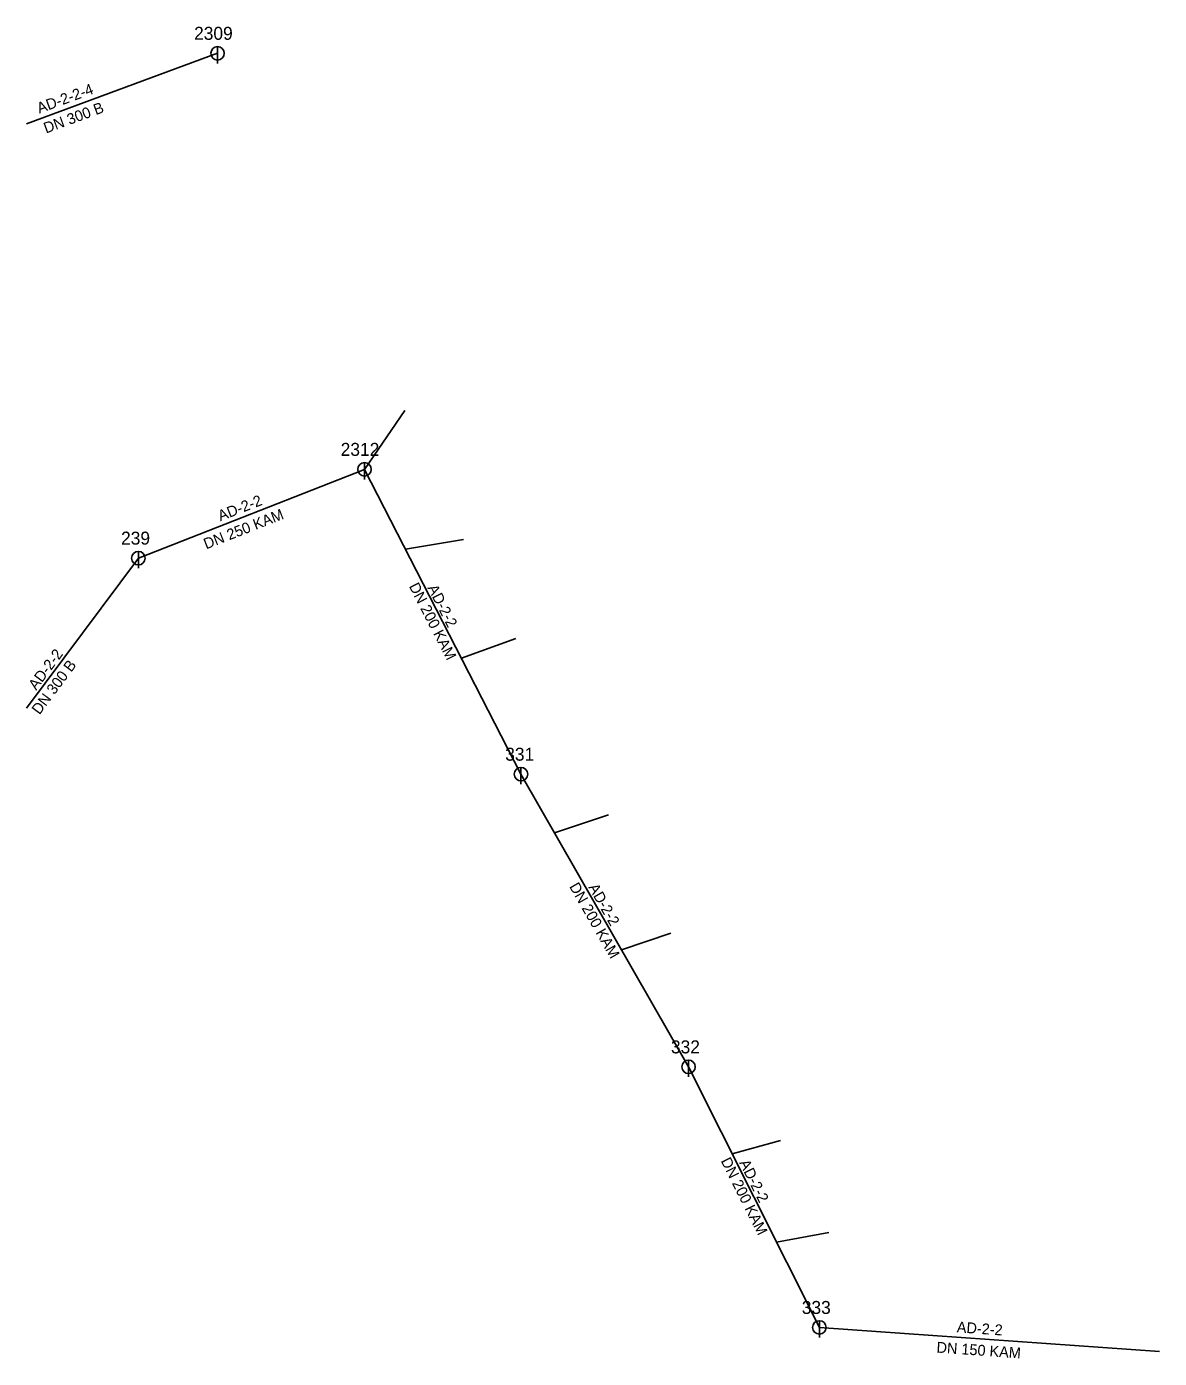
# Model space of a CAD drawing. Extents: x -443519 to -443022, y -1121479 to -1120928.
# Drawn here: x -443519.1 to -443351.1, y -1121125.3 to -1120927.9 of the extents above; entities that cross this region are included whole.
import ezdxf

# ---------------------------------------------------------------- set-up
doc = ezdxf.new("R2010")
doc.units = 0
for name, color, linetype in [('_pripojka_kanal_jednotna_priblizne_', 7, 'Continuous'), ('_stoka_jednotna_smvak_prevzato_z_dokumentace_', 7, 'Continuous'), ('Default', 7, 'Continuous'), ('MoLevel 119', 7, 'Continuous'), ('MoLevel 120', 7, 'Continuous'), ('MoLevel 68', 7, 'Continuous'), ('MoLevel 69', 7, 'Continuous')]:
    doc.layers.add(name, color=color, linetype=linetype)

# ---------------------------------------------------------------- blocks, each defined once
blk = doc.blocks.new('_sachta_kanal_prevzato_z_dokumentace_')
at = {"layer": 'Default'}
blk.add_line((0, 0.00005), (0, -0.000075), dxfattribs=at)
blk.add_circle((0, 0), 0.00005, dxfattribs=at)

msp = doc.modelspace()

# ---------------------------------------------------------------- linework, layer by layer
at = {"layer": '_pripojka_kanal_jednotna_priblizne_'}
for p, q in [((-443463.04, -1120984.82), (-443469.02, -1120993.53)), ((-443454.32, -1121003.94), (-443462.94, -1121005.37)), ((-443446.56, -1121018.62), (-443454.64, -1121021.52)), ((-443432.83, -1121044.74), (-443440.84, -1121047.4)), ((-443423.58, -1121062.3), (-443430.89, -1121064.78)), ((-443407.33, -1121093.04), (-443414.49, -1121095)), ((-443400.15, -1121106.66), (-443407.91, -1121108.09))]:
    msp.add_line(p, q, dxfattribs=at)
at = {"layer": '_stoka_jednotna_smvak_prevzato_z_dokumentace_'}
for p, q in [((-443490.81, -1120931.85), (-443519.12, -1120942.3)), ((-443469.02, -1120993.53), (-443502.55, -1121006.69)), ((-443445.81, -1121038.72), (-443469.02, -1120993.53)), ((-443502.55, -1121006.69), (-443519.12, -1121028.91)), ((-443420.96, -1121082.11), (-443445.81, -1121038.72)), ((-443401.56, -1121120.74), (-443420.96, -1121082.11)), ((-443351.14, -1121124.29), (-443401.56, -1121120.74))]:
    msp.add_line(p, q, dxfattribs=at)

# ---------------------------------------------------------------- block references
at = {"layer": 'MoLevel 119', "xscale": 20000, "yscale": 20000}
for p in [(-443490.81, -1120931.85), (-443469.02, -1120993.53), (-443502.55, -1121006.69), (-443445.81, -1121038.72), (-443420.96, -1121082.11), (-443401.56, -1121120.74)]:
    msp.add_blockref('_sachta_kanal_prevzato_z_dokumentace_', p, dxfattribs=at)

# ---------------------------------------------------------------- texts
at = {"layer": 'MoLevel 120'}
for s, p in [('2309', (-443494.29, -1120929.85)), ('2312', (-443472.55, -1120991.53)), ('239', (-443505.12, -1121004.69)), ('331', (-443448.15, -1121036.72)), ('332', (-443423.57, -1121080.11)), ('333', (-443404.17, -1121118.74))]:
    msp.add_text(s, height=1.926, dxfattribs=at).set_placement(p)
at = {"layer": 'MoLevel 68'}
for s, rotation, p in [('DN 300 B', 20.2492, (-443516.25, -1120943.75)), ('DN 250 KAM', 21.4272, (-443492.5, -1121005.4)), ('DN 200 KAM', 297.1865, (-443462.47, -1121010.84)), ('DN 300 B', 53.2854, (-443517.22, -1121030)), ('DN 200 KAM', 299.7996, (-443438.7, -1121055.36)), ('DN 200 KAM', 296.6661, (-443416.22, -1121096.04)), ('DN 150 KAM', 355.9725, (-443384.23, -1121124.46))]:
    msp.add_text(s, height=1.605, rotation=rotation, dxfattribs=at).set_placement(p)
at = {"layer": 'MoLevel 69'}
for s, rotation, p in [('AD-2-2-4', 20.2492, (-443517.24, -1120940.8)), ('AD-2-2', 21.4272, (-443490.38, -1121001.24)), ('AD-2-2', 297.1865, (-443459.71, -1121011.09)), ('AD-2-2', 53.2854, (-443517.71, -1121026.37)), ('AD-2-2', 299.7996, (-443435.87, -1121055.48)), ('AD-2-2', 296.6661, (-443413.48, -1121096.32)), ('AD-2-2', 355.9725, (-443381.22, -1121121.46))]:
    msp.add_text(s, height=1.605, rotation=rotation, dxfattribs=at).set_placement(p)

doc.saveas('drawing.dxf')
